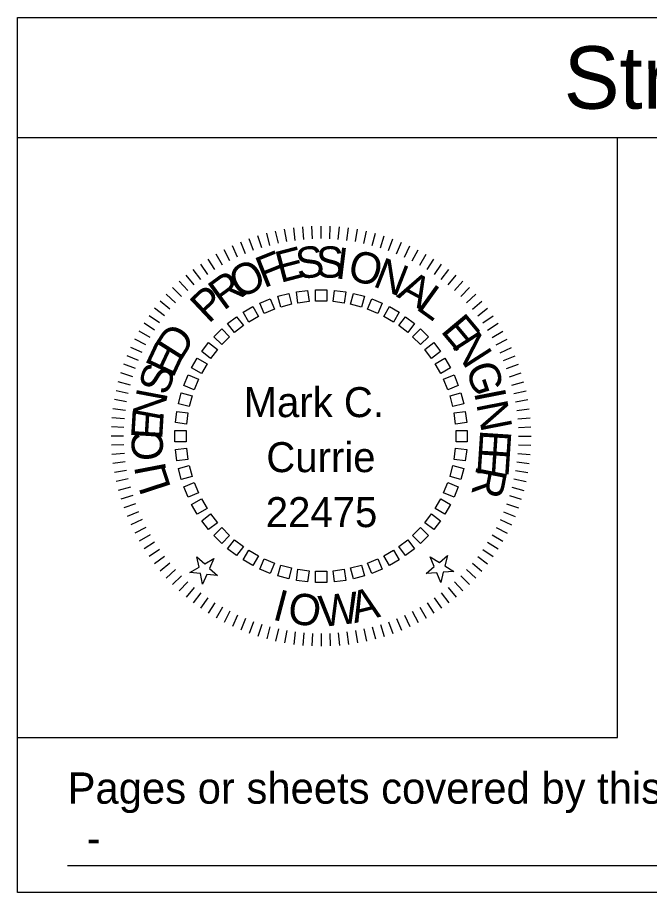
# Model space of a CAD drawing. Extents: x -0.84 to 4.97, y -1.01 to 2.42.
# Drawn here: x 2.9797 to 3.1904, y -0.9865 to -0.6948 of the extents above; entities that cross this region are included whole.
import ezdxf

# ---------------------------------------------------------------- set-up
doc = ezdxf.new("R2010")
doc.units = 0
for name, color, linetype in [('Level 1', 7, 'Continuous'), ('Level 2', 7, 'Continuous'), ('SheetGridMajor', 7, 'Continuous'), ('SheetGridMinor', 7, 'Continuous'), ('SheetText', 7, 'Continuous')]:
    doc.layers.add(name, color=color, linetype=linetype)

msp = doc.modelspace()

# ---------------------------------------------------------------- linework, layer by layer
at = {"layer": 'Level 1'}
for p, q in [((3.06387, -0.77078), (3.06279, -0.76675)), ((3.06666, -0.77009), (3.06575, -0.76603)), ((3.06947, -0.76953), (3.06875, -0.76543)), ((3.07231, -0.7691), (3.07177, -0.76497)), ((3.07517, -0.76878), (3.0748, -0.76463)), ((3.07803, -0.7686), (3.07785, -0.76443)), ((3.08091, -0.76853), (3.08091, -0.76437)), ((3.08378, -0.7686), (3.08396, -0.76443)), ((3.08664, -0.76878), (3.08701, -0.76463)), ((3.0895, -0.7691), (3.09004, -0.76497)), ((3.09234, -0.76953), (3.09306, -0.76543)), ((3.09515, -0.7701), (3.09606, -0.76603)), ((3.09794, -0.77078), (3.09902, -0.76675)), ((3.05571, -0.77355), (3.05412, -0.7697)), ((3.05839, -0.7725), (3.05696, -0.76859)), ((3.06111, -0.77158), (3.05986, -0.76761)), ((3.1007, -0.77158), (3.10195, -0.76761)), ((3.10342, -0.7725), (3.10485, -0.76859)), ((3.1061, -0.77355), (3.10769, -0.7697)), ((3.05051, -0.77597), (3.04858, -0.77228)), ((3.05308, -0.7747), (3.05132, -0.77093)), ((3.10873, -0.7747), (3.11049, -0.77093)), ((3.1113, -0.77597), (3.11323, -0.77228)), ((3.04553, -0.77884), (3.04329, -0.77533)), ((3.04799, -0.77735), (3.04591, -0.77375)), ((3.11382, -0.77735), (3.1159, -0.77375)), ((3.11628, -0.77884), (3.11852, -0.77533)), ((3.04314, -0.78044), (3.04076, -0.77703)), ((3.11867, -0.78044), (3.12105, -0.77703)), ((3.03859, -0.78394), (3.03591, -0.78074)), ((3.04083, -0.78214), (3.03829, -0.77883)), ((3.12098, -0.78214), (3.12352, -0.77883)), ((3.12322, -0.78394), (3.1259, -0.78074)), ((3.03643, -0.78583), (3.03361, -0.78276)), ((3.12538, -0.78583), (3.1282, -0.78276)), ((3.03237, -0.78989), (3.0293, -0.78708)), ((3.03435, -0.78782), (3.03141, -0.78487)), ((3.12746, -0.78782), (3.1304, -0.78487)), ((3.12944, -0.78989), (3.13251, -0.78708)), ((3.03047, -0.79205), (3.02728, -0.78937)), ((3.13134, -0.79205), (3.13453, -0.78937)), ((3.02868, -0.79429), (3.02537, -0.79175)), ((3.13313, -0.79429), (3.13644, -0.79175)), ((3.02698, -0.79661), (3.02356, -0.79422)), ((3.13483, -0.79661), (3.13825, -0.79422)), ((3.02538, -0.79899), (3.02187, -0.79676)), ((3.13643, -0.799), (3.13994, -0.79676)), ((3.02251, -0.80397), (3.01881, -0.80204)), ((3.02389, -0.80145), (3.02028, -0.79937)), ((3.13792, -0.80145), (3.14153, -0.79937)), ((3.1393, -0.80397), (3.143, -0.80205)), ((3.02124, -0.80654), (3.01746, -0.80478)), ((3.14057, -0.80655), (3.14435, -0.80478)), ((3.02008, -0.80917), (3.01623, -0.80758)), ((3.14173, -0.80917), (3.14558, -0.80758)), ((3.01904, -0.81185), (3.01513, -0.81043)), ((3.14277, -0.81185), (3.14668, -0.81043)), ((3.01812, -0.81457), (3.01415, -0.81332)), ((3.14369, -0.81457), (3.14766, -0.81332)), ((3.01732, -0.81733), (3.01329, -0.81625)), ((3.14449, -0.81733), (3.14852, -0.81625)), ((3.01663, -0.82012), (3.01256, -0.81922)), ((3.14518, -0.82012), (3.14925, -0.81922)), ((3.01607, -0.82293), (3.01197, -0.82221)), ((3.14574, -0.82294), (3.14984, -0.82221)), ((3.01564, -0.82577), (3.0115, -0.82523)), ((3.14617, -0.82577), (3.15031, -0.82523)), ((3.01532, -0.82863), (3.01117, -0.82827)), ((3.14649, -0.82863), (3.15064, -0.82827)), ((3.01513, -0.8315), (3.01097, -0.83131)), ((3.14668, -0.8315), (3.15084, -0.83132)), ((3.01507, -0.83437), (3.0109, -0.83437)), ((3.14674, -0.83437), (3.1509, -0.83437)), ((3.01513, -0.83724), (3.01097, -0.83742)), ((3.14667, -0.83724), (3.15084, -0.83742)), ((3.01532, -0.84011), (3.01117, -0.84047)), ((3.14649, -0.84011), (3.15064, -0.84047)), ((3.01563, -0.84296), (3.0115, -0.84351)), ((3.01607, -0.8458), (3.01197, -0.84652)), ((3.14574, -0.8458), (3.14984, -0.84652)), ((3.14617, -0.84296), (3.15031, -0.84351)), ((3.01663, -0.84862), (3.01256, -0.84952)), ((3.14518, -0.84862), (3.14924, -0.84952)), ((3.01732, -0.85141), (3.01329, -0.85249)), ((3.14449, -0.85141), (3.14852, -0.85249)), ((3.01812, -0.85416), (3.01414, -0.85542)), ((3.14369, -0.85417), (3.14766, -0.85542)), ((3.01904, -0.85688), (3.01513, -0.85831)), ((3.14277, -0.85689), (3.14668, -0.85831)), ((3.02008, -0.85956), (3.01623, -0.86116)), ((3.14173, -0.85956), (3.14558, -0.86116)), ((3.02124, -0.86219), (3.01746, -0.86395)), ((3.14057, -0.86219), (3.14435, -0.86395)), ((3.02251, -0.86477), (3.01881, -0.86669)), ((3.1393, -0.86477), (3.14299, -0.86669)), ((3.02389, -0.86728), (3.02028, -0.86937)), ((3.13792, -0.86729), (3.14153, -0.86937)), ((3.02538, -0.86974), (3.02187, -0.87198)), ((3.13643, -0.86974), (3.13994, -0.87198)), ((3.02698, -0.87213), (3.02356, -0.87452)), ((3.02868, -0.87445), (3.02537, -0.87698)), ((3.13313, -0.87445), (3.13644, -0.87698)), ((3.13483, -0.87213), (3.13824, -0.87452)), ((3.03047, -0.87669), (3.02728, -0.87936)), ((3.13134, -0.87669), (3.13453, -0.87936)), ((3.03237, -0.87884), (3.02929, -0.88166)), ((3.12944, -0.87885), (3.13251, -0.88166)), ((3.03435, -0.88092), (3.03141, -0.88387)), ((3.03643, -0.88291), (3.03361, -0.88598)), ((3.12538, -0.88291), (3.12819, -0.88598)), ((3.12746, -0.88092), (3.1304, -0.88387)), ((3.03859, -0.8848), (3.03591, -0.88799)), ((3.04083, -0.8866), (3.03829, -0.8899)), ((3.12098, -0.8866), (3.12352, -0.8899)), ((3.12322, -0.8848), (3.1259, -0.88799)), ((3.04314, -0.8883), (3.04075, -0.89171)), ((3.11866, -0.8883), (3.12105, -0.89171)), ((3.04553, -0.88989), (3.04329, -0.89341)), ((3.04799, -0.89138), (3.0459, -0.89499)), ((3.11382, -0.89138), (3.1159, -0.89499)), ((3.11628, -0.88989), (3.11851, -0.89341)), ((3.05051, -0.89276), (3.04858, -0.89646)), ((3.05308, -0.89403), (3.05132, -0.89781)), ((3.05571, -0.89519), (3.05412, -0.89904)), ((3.1061, -0.89519), (3.10769, -0.89904)), ((3.10873, -0.89403), (3.11049, -0.89781)), ((3.1113, -0.89276), (3.11323, -0.89646)), ((3.05839, -0.89623), (3.05696, -0.90015)), ((3.06111, -0.89715), (3.05985, -0.90113)), ((3.06387, -0.89796), (3.06279, -0.90198)), ((3.09794, -0.89796), (3.09902, -0.90198)), ((3.1007, -0.89715), (3.10195, -0.90113)), ((3.10342, -0.89623), (3.10485, -0.90015)), ((3.06666, -0.89864), (3.06575, -0.90271)), ((3.06947, -0.8992), (3.06875, -0.9033)), ((3.07231, -0.89964), (3.07177, -0.90377)), ((3.07517, -0.89995), (3.0748, -0.9041)), ((3.07803, -0.90014), (3.07785, -0.9043)), ((3.0809, -0.9002), (3.0809, -0.90437)), ((3.08378, -0.90014), (3.08396, -0.9043)), ((3.08664, -0.89995), (3.08701, -0.9041)), ((3.0895, -0.89964), (3.09004, -0.90377)), ((3.09234, -0.8992), (3.09306, -0.90331)), ((3.09515, -0.89864), (3.09605, -0.90271))]:
    msp.add_line(p, q, dxfattribs=at)
for points in [[(3.07107, -0.79041), (3.06745, -0.79139), (3.06648, -0.78776), (3.0701, -0.78679)], [(3.07689, -0.78951), (3.07317, -0.79), (3.07268, -0.78628), (3.0764, -0.78579)], [(3.08278, -0.78937), (3.07903, -0.78937), (3.07903, -0.78562), (3.08278, -0.78562)], [(3.08864, -0.79), (3.08492, -0.78951), (3.08541, -0.78579), (3.08913, -0.78628)], [(3.09436, -0.79139), (3.09074, -0.79042), (3.09171, -0.78679), (3.09533, -0.78776)], [(3.06542, -0.79207), (3.06195, -0.79351), (3.06052, -0.79005), (3.06398, -0.78861)], [(3.09986, -0.79351), (3.09639, -0.79208), (3.09783, -0.78861), (3.10129, -0.79005)], [(3.06003, -0.79446), (3.05678, -0.79633), (3.05491, -0.79309), (3.05815, -0.79121)], [(3.10503, -0.79633), (3.10178, -0.79446), (3.10366, -0.79121), (3.1069, -0.79309)], [(3.055, -0.79752), (3.05202, -0.79981), (3.04974, -0.79683), (3.05271, -0.79455)], [(3.10979, -0.79981), (3.10681, -0.79752), (3.10909, -0.79455), (3.11207, -0.79683)], [(3.05041, -0.80122), (3.04776, -0.80387), (3.04511, -0.80122), (3.04776, -0.79857)], [(3.11405, -0.80387), (3.1114, -0.80122), (3.11405, -0.79857), (3.1167, -0.80122)], [(3.04634, -0.80549), (3.04406, -0.80846), (3.04109, -0.80618), (3.04337, -0.8032)], [(3.11775, -0.80846), (3.11546, -0.80549), (3.11844, -0.8032), (3.12072, -0.80618)], [(3.04287, -0.81024), (3.041, -0.81349), (3.03775, -0.81162), (3.03962, -0.80837)], [(3.12081, -0.81349), (3.11894, -0.81024), (3.12219, -0.80837), (3.12406, -0.81162)], [(3.04005, -0.81541), (3.03861, -0.81888), (3.03515, -0.81744), (3.03658, -0.81398)], [(3.1232, -0.81888), (3.12176, -0.81541), (3.12523, -0.81398), (3.12666, -0.81744)], [(3.03792, -0.82091), (3.03695, -0.82453), (3.03333, -0.82356), (3.0343, -0.81994)], [(3.12486, -0.82453), (3.12389, -0.82091), (3.12751, -0.81994), (3.12848, -0.82356)], [(3.03653, -0.82663), (3.03605, -0.83035), (3.03233, -0.82986), (3.03282, -0.82615)], [(3.12576, -0.83035), (3.12527, -0.82663), (3.12899, -0.82614), (3.12948, -0.82986)], [(3.0359, -0.83249), (3.0359, -0.83624), (3.03215, -0.83624), (3.03215, -0.83249)], [(3.1259, -0.83624), (3.1259, -0.83249), (3.12965, -0.83249), (3.12965, -0.83624)], [(3.03604, -0.83838), (3.03653, -0.8421), (3.03282, -0.84259), (3.03233, -0.83887)], [(3.12528, -0.8421), (3.12576, -0.83838), (3.12948, -0.83887), (3.12899, -0.84259)], [(3.03695, -0.8442), (3.03792, -0.84783), (3.0343, -0.8488), (3.03333, -0.84518)], [(3.12389, -0.84783), (3.12486, -0.8442), (3.12848, -0.84518), (3.12751, -0.8488)], [(3.03861, -0.84986), (3.04005, -0.85332), (3.03658, -0.85476), (3.03515, -0.85129)], [(3.12176, -0.85332), (3.1232, -0.84986), (3.12666, -0.85129), (3.12523, -0.85476)], [(3.041, -0.85524), (3.04287, -0.85849), (3.03962, -0.86037), (3.03775, -0.85712)], [(3.11894, -0.85849), (3.12081, -0.85524), (3.12406, -0.85712), (3.12219, -0.86037)], [(3.04406, -0.86028), (3.04635, -0.86325), (3.04337, -0.86553), (3.04109, -0.86256)], [(3.11546, -0.86325), (3.11775, -0.86027), (3.12072, -0.86256), (3.11844, -0.86553)], [(3.04776, -0.86486), (3.05041, -0.86751), (3.04776, -0.87017), (3.04511, -0.86751)], [(3.1114, -0.86751), (3.11405, -0.86486), (3.1167, -0.86751), (3.11405, -0.87017)], [(3.05202, -0.86893), (3.055, -0.87121), (3.05271, -0.87419), (3.04974, -0.8719)], [(3.10681, -0.87121), (3.10979, -0.86893), (3.11207, -0.8719), (3.10909, -0.87419)], [(3.03947, -0.8746), (3.0421, -0.87697), (3.04518, -0.8752), (3.04373, -0.87844), (3.04637, -0.88081), (3.04284, -0.88044), (3.0414, -0.88368), (3.04066, -0.88021), (3.03714, -0.87984), (3.04021, -0.87806)], [(3.05678, -0.8724), (3.06003, -0.87428), (3.05815, -0.87753), (3.05491, -0.87565)], [(3.10178, -0.87428), (3.10503, -0.8724), (3.1069, -0.87565), (3.10366, -0.87752)], [(3.11732, -0.87458), (3.12033, -0.87646), (3.12304, -0.87418), (3.12219, -0.87762), (3.12519, -0.8795), (3.12166, -0.87975), (3.1208, -0.88319), (3.11947, -0.8799), (3.11593, -0.88015), (3.11865, -0.87787)], [(3.06195, -0.87523), (3.06542, -0.87666), (3.06398, -0.88013), (3.06052, -0.87869)], [(3.06745, -0.87735), (3.07107, -0.87832), (3.0701, -0.88194), (3.06648, -0.88097)], [(3.09074, -0.87832), (3.09436, -0.87735), (3.09533, -0.88097), (3.09171, -0.88194)], [(3.09639, -0.87666), (3.09986, -0.87523), (3.10129, -0.87869), (3.09783, -0.88013)], [(3.07317, -0.87874), (3.07689, -0.87923), (3.0764, -0.88295), (3.07268, -0.88246)], [(3.07903, -0.87937), (3.08278, -0.87937), (3.08278, -0.88312), (3.07903, -0.88312)], [(3.08492, -0.87923), (3.08864, -0.87874), (3.08913, -0.88246), (3.08541, -0.88295)]]:
    msp.add_lwpolyline(points, close=True, dxfattribs=at)
at = {"layer": 'SheetGridMajor'}
for p, q in [((2.97968, -0.73482), (3.60468, -0.73482)), ((3.17968, -0.93482), (3.17968, -0.73482)), ((2.97968, -0.93482), (3.17968, -0.93482))]:
    msp.add_line(p, q, dxfattribs=at)
msp.add_lwpolyline([(2.97968, -0.69482), (3.60468, -0.69482), (3.60468, -0.98649), (2.97968, -0.98649)], close=True, dxfattribs=at)
at = {"layer": 'SheetGridMinor'}
msp.add_line((2.9964, -0.97751), (3.58802, -0.97751), dxfattribs=at)

# ---------------------------------------------------------------- texts
at = {"layer": 'Level 1'}
for s, rotation, p in [('F', 21.7736, (3.06185, -0.78511)), ('E', 14.5823, (3.06731, -0.78333)), ('S', 7.3911, (3.07316, -0.78212)), ('S', 0.1998, (3.07925, -0.78156)), ('I', 353.0085, (3.08536, -0.78171)), ('O', 345.8172, (3.0893, -0.78202)), ('N', 338.6259, (3.09783, -0.78428)), ('O', 28.9649, (3.05392, -0.78894)), ('R', 36.1562, (3.04838, -0.79272)), ('A', 331.4346, (3.10584, -0.78781)), ('L', 324.2434, (3.11218, -0.79181)), ('P', 43.3475, (3.04342, -0.79713)), ('E', 309.8608, (3.1205, -0.79939)), ('D', 57.7301, (3.03395, -0.80981)), ('N', 302.6695, (3.12421, -0.80407)), ('E', 64.9213, (3.03152, -0.81529)), ('S', 72.1126, (3.02968, -0.82113)), ('G', 288.2869, (3.12897, -0.81151)), ('N', 79.3039, (3.02803, -0.82975)), ('I', 281.0956, (3.13185, -0.81972)), ('N', 281.0956, (3.13261, -0.82359)), ('E', 86.4952, (3.02791, -0.83575)), ('C', 93.6865, (3.0285, -0.84233)), ('E', 266.2773, (3.13398, -0.83207)), ('E', 266.2773, (3.13359, -0.83804)), ('I', 100.8778, (3.0294, -0.84618)), ('L', 108.069, (3.03097, -0.85159)), ('R', 259.086, (3.13284, -0.84396)), ('I', 345.2906, (3.06434, -0.89539)), ('O', 352.4819, (3.06944, -0.89663)), ('W', 6.8645, (3.08084, -0.89806)), ('A', 14.0557, (3.09202, -0.89677))]:
    msp.add_text(s, height=0.01042, rotation=rotation, dxfattribs=at).set_placement(p)
at = {"layer": 'Level 2'}
for s, p in [('Mark C.', (3.05507, -0.82803)), ('Currie', (3.06264, -0.84637)), ('22475', (3.06246, -0.8647))]:
    msp.add_text(s, height=0.01, dxfattribs=at).set_placement(p)
at = {"layer": 'SheetText'}
for s, height, p in [('Structural Design', 0.0208333, (3.16182, -0.72524)), ('Pages or sheets covered by this seal:', 0.0104167, (2.9964, -0.95689)), ('-', 0.0104, (3.00277, -0.97349))]:
    msp.add_text(s, height=height, dxfattribs=at).set_placement(p)

doc.saveas('drawing.dxf')
